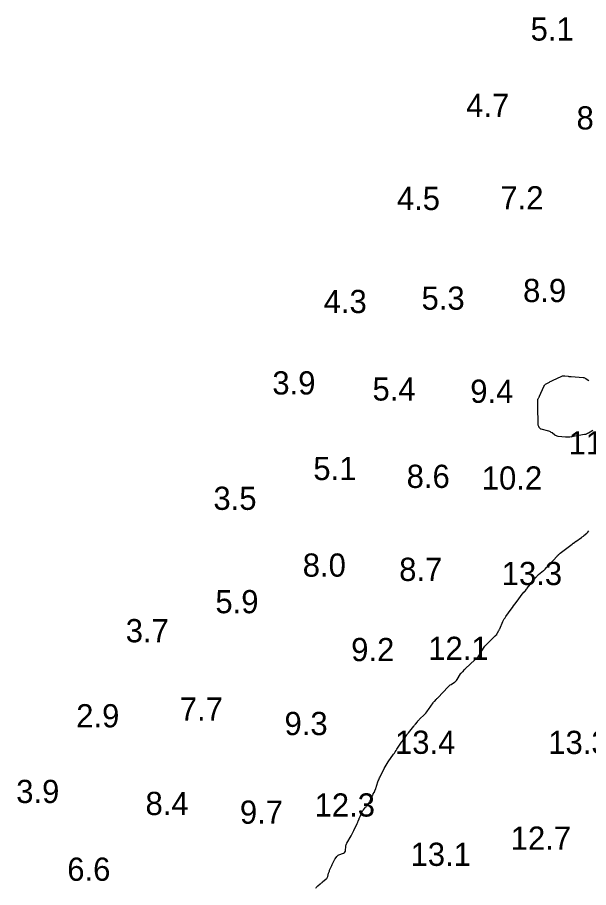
# Model space of a CAD drawing. Extents: x 815352 to 820877, y 582403 to 597439.
# Drawn here: x 819617 to 819740.1, y 588634.3 to 588821.8 of the extents above; entities that cross this region are included whole.
import ezdxf

# ---------------------------------------------------------------- set-up
doc = ezdxf.new("R2010")
doc.units = 0
doc.layers.add('V-CONT-EL12', color=7, linetype='Continuous')
doc.layers.add('V-TOPO-SOUN', color=7, linetype='Continuous')

msp = doc.modelspace()

# ---------------------------------------------------------------- linework, layer by layer
at = {"layer": 'V-CONT-EL12'}
for points in [[(819741, 588732.76), (819740.07, 588732.22), (819739.87, 588732.11), (819739.65, 588732.02), (819739.43, 588731.95), (819739.21, 588731.9), (819736.41, 588731.41), (819736.08, 588731.36), (819735.76, 588731.34), (819735.43, 588731.34), (819735.1, 588731.36), (819733.52, 588731.52), (819733.33, 588731.55), (819733.16, 588731.61), (819732.99, 588731.69), (819732.83, 588731.8), (819732.22, 588732.27), (819732.06, 588732.38), (819731.9, 588732.47), (819731.72, 588732.55), (819731.54, 588732.61), (819729.89, 588733.06), (819729.83, 588733.08), (819729.76, 588733.11), (819729.71, 588733.16), (819729.66, 588733.21), (819729.47, 588733.44), (819729.43, 588733.49), (819729.39, 588733.55), (819729.36, 588733.6), (819729.34, 588733.67), (819729.25, 588733.92), (819729.24, 588733.98), (819729.22, 588734.04), (819729.21, 588734.11), (819729.21, 588734.17), (819729.13, 588737.92), (819729.13, 588738.07), (819729.13, 588738.23), (819729.13, 588738.38), (819729.13, 588738.54), (819729.13, 588739.32), (819729.13, 588739.4), (819729.15, 588739.47), (819729.17, 588739.54), (819729.21, 588739.61), (819729.38, 588739.87), (819729.42, 588739.94), (819729.46, 588740.01), (819729.5, 588740.07), (819729.53, 588740.15), (819730.48, 588742.28), (819730.57, 588742.45), (819730.69, 588742.6), (819730.82, 588742.73), (819730.98, 588742.83), (819731.66, 588743.22), (819731.83, 588743.31), (819732, 588743.4), (819732.17, 588743.49), (819732.35, 588743.57), (819734.34, 588744.47), (819734.5, 588744.53), (819734.66, 588744.57), (819734.83, 588744.58), (819735, 588744.57), (819735.68, 588744.47), (819735.85, 588744.45), (819736.02, 588744.43), (819736.19, 588744.41), (819736.36, 588744.4), (819738.92, 588744.22), (819739.08, 588744.2), (819739.23, 588744.16), (819739.37, 588744.09), (819739.5, 588744.01), (819740.01, 588743.61), (819740.14, 588743.51)], [(819681.29, 588634.15), (819681.4, 588634.27), (819681.51, 588634.39), (819681.63, 588634.51), (819681.76, 588634.62), (819682.28, 588635.04), (819682.41, 588635.15), (819682.54, 588635.25), (819682.67, 588635.36), (819682.79, 588635.47), (819683.54, 588636.11), (819683.66, 588636.23), (819683.76, 588636.37), (819683.84, 588636.51), (819683.89, 588636.67), (819684.08, 588637.35), (819684.12, 588637.51), (819684.18, 588637.67), (819684.24, 588637.82), (819684.3, 588637.98), (819684.57, 588638.59), (819684.64, 588638.75), (819684.7, 588638.9), (819684.77, 588639.05), (819684.84, 588639.21), (819685.18, 588639.98), (819685.24, 588640.11), (819685.31, 588640.24), (819685.39, 588640.36), (819685.48, 588640.48), (819685.83, 588640.94), (819685.93, 588641.05), (819686.03, 588641.14), (819686.15, 588641.22), (819686.28, 588641.28), (819687.31, 588641.7), (819687.48, 588641.79), (819687.6, 588641.92), (819687.68, 588642.08), (819687.71, 588642.26), (819687.76, 588643.08), (819687.79, 588643.29), (819687.84, 588643.48), (819687.91, 588643.67), (819688, 588643.85), (819688.93, 588645.39), (819689.1, 588645.67), (819689.25, 588645.96), (819689.4, 588646.25), (819689.54, 588646.55), (819690.25, 588648.1), (819690.3, 588648.22), (819690.35, 588648.34), (819690.4, 588648.46), (819690.45, 588648.58), (819690.64, 588649.06), (819690.69, 588649.19), (819690.74, 588649.31), (819690.79, 588649.43), (819690.84, 588649.55), (819691.22, 588650.41), (819691.29, 588650.57), (819691.38, 588650.72), (819691.47, 588650.86), (819691.58, 588650.99), (819692.05, 588651.57), (819692.14, 588651.68), (819692.23, 588651.79), (819692.32, 588651.9), (819692.41, 588652.02), (819692.75, 588652.48), (819692.83, 588652.6), (819692.9, 588652.72), (819692.97, 588652.84), (819693.03, 588652.97), (819693.53, 588654.12), (819693.57, 588654.2), (819693.61, 588654.28), (819693.66, 588654.37), (819693.7, 588654.45), (819693.89, 588654.76), (819693.94, 588654.85), (819693.98, 588654.93), (819694.02, 588655.01), (819694.05, 588655.1), (819694.24, 588655.64), (819694.28, 588655.76), (819694.32, 588655.87), (819694.36, 588655.99), (819694.4, 588656.11), (819694.79, 588657.23), (819694.88, 588657.45), (819694.97, 588657.67), (819695.06, 588657.89), (819695.17, 588658.11), (819696.08, 588659.91), (819696.27, 588660.28), (819696.47, 588660.64), (819696.69, 588660.99), (819696.92, 588661.33), (819698.07, 588662.98), (819698.26, 588663.25), (819698.44, 588663.53), (819698.62, 588663.8), (819698.81, 588664.07), (819699.8, 588665.59), (819699.84, 588665.66), (819699.89, 588665.72), (819699.93, 588665.79), (819699.98, 588665.85), (819700.2, 588666.16), (819700.23, 588666.2), (819700.26, 588666.24), (819700.29, 588666.28), (819700.32, 588666.32), (819700.44, 588666.47), (819700.46, 588666.5), (819700.49, 588666.54), (819700.52, 588666.58), (819700.55, 588666.62), (819700.95, 588667.17), (819701.02, 588667.28), (819701.1, 588667.38), (819701.18, 588667.49), (819701.26, 588667.59), (819702.41, 588669.02), (819702.51, 588669.15), (819702.61, 588669.27), (819702.71, 588669.39), (819702.8, 588669.51), (819703.2, 588670), (819703.3, 588670.12), (819703.4, 588670.24), (819703.51, 588670.36), (819703.61, 588670.47), (819704.78, 588671.64), (819705, 588671.88), (819705.22, 588672.12), (819705.42, 588672.38), (819705.61, 588672.64), (819706.63, 588674.1), (819706.7, 588674.19), (819706.77, 588674.29), (819706.85, 588674.38), (819706.93, 588674.46), (819707.26, 588674.81), (819707.34, 588674.9), (819707.42, 588674.98), (819707.51, 588675.07), (819707.59, 588675.16), (819709.81, 588677.53), (819709.96, 588677.68), (819710.12, 588677.82), (819710.28, 588677.95), (819710.46, 588678.06), (819711.18, 588678.51), (819711.35, 588678.63), (819711.5, 588678.77), (819711.64, 588678.92), (819711.76, 588679.09), (819712.49, 588680.31), (819712.53, 588680.38), (819712.58, 588680.44), (819712.63, 588680.5), (819712.69, 588680.55), (819712.94, 588680.76), (819713, 588680.81), (819713.05, 588680.86), (819713.11, 588680.92), (819713.16, 588680.98), (819713.36, 588681.24), (819713.41, 588681.3), (819713.47, 588681.36), (819713.52, 588681.42), (819713.58, 588681.48), (819715.61, 588683.37), (819715.66, 588683.41), (819715.71, 588683.46), (819715.76, 588683.5), (819715.81, 588683.54), (819716.03, 588683.69), (819716.09, 588683.73), (819716.13, 588683.77), (819716.18, 588683.82), (819716.22, 588683.88), (819716.44, 588684.24), (819716.49, 588684.31), (819716.54, 588684.39), (819716.59, 588684.47), (819716.64, 588684.55), (819717.44, 588685.83), (819717.59, 588686.07), (819717.76, 588686.29), (819717.94, 588686.5), (819718.14, 588686.71), (819719.99, 588688.49), (819720.03, 588688.53), (819720.06, 588688.57), (819720.1, 588688.61), (819720.13, 588688.64), (819720.29, 588688.82), (819720.32, 588688.85), (819720.34, 588688.88), (819720.36, 588688.91), (819720.37, 588688.94), (819720.43, 588689.07), (819720.45, 588689.1), (819720.46, 588689.13), (819720.48, 588689.16), (819720.5, 588689.19), (819720.76, 588689.66), (819720.8, 588689.75), (819720.85, 588689.84), (819720.9, 588689.93), (819720.94, 588690.02), (819721.65, 588691.58), (819721.78, 588691.87), (819721.94, 588692.15), (819722.1, 588692.42), (819722.28, 588692.68), (819723.43, 588694.29), (819723.69, 588694.64), (819723.94, 588695), (819724.2, 588695.35), (819724.46, 588695.7), (819726.02, 588697.76), (819726.06, 588697.81), (819726.1, 588697.86), (819726.15, 588697.91), (819726.19, 588697.95), (819726.38, 588698.14), (819726.42, 588698.18), (819726.47, 588698.23), (819726.51, 588698.28), (819726.55, 588698.33), (819726.71, 588698.56), (819726.75, 588698.61), (819726.79, 588698.67), (819726.83, 588698.72), (819726.87, 588698.77), (819727.84, 588700.03), (819727.95, 588700.18), (819728.07, 588700.32), (819728.19, 588700.47), (819728.31, 588700.61), (819728.78, 588701.19), (819728.91, 588701.33), (819729.04, 588701.46), (819729.17, 588701.59), (819729.31, 588701.71), (819730.4, 588702.58), (819730.49, 588702.65), (819730.57, 588702.73), (819730.65, 588702.81), (819730.73, 588702.89), (819731.02, 588703.22), (819731.1, 588703.3), (819731.17, 588703.38), (819731.25, 588703.47), (819731.32, 588703.55), (819733.39, 588705.76), (819733.42, 588705.8), (819733.45, 588705.83), (819733.48, 588705.86), (819733.51, 588705.9), (819733.63, 588706.03), (819733.65, 588706.06), (819733.68, 588706.09), (819733.71, 588706.12), (819733.74, 588706.14), (819733.87, 588706.24), (819733.9, 588706.26), (819733.93, 588706.28), (819733.96, 588706.31), (819733.99, 588706.33), (819736.55, 588708.31), (819736.62, 588708.36), (819736.69, 588708.41), (819736.76, 588708.46), (819736.82, 588708.5), (819737.1, 588708.68), (819737.17, 588708.73), (819737.24, 588708.78), (819737.31, 588708.82), (819737.38, 588708.87), (819738.6, 588709.74), (819738.73, 588709.83), (819738.86, 588709.93), (819738.98, 588710.02), (819739.1, 588710.13), (819739.7, 588710.64), (819739.76, 588710.69), (819739.82, 588710.75), (819739.87, 588710.8), (819739.92, 588710.86), (819740.16, 588711.14)]]:
    msp.add_lwpolyline(points, dxfattribs=at)

# ---------------------------------------------------------------- texts
at = {"layer": 'V-TOPO-SOUN'}
for s, p in [('5.1', (819727.6, 588816.82)), ('4.7', (819713.71, 588800.35)), ('8.8', (819737.5, 588797.66)), ('4.5', (819698.78, 588780.3)), ('7.2', (819721.09, 588780.44)), ('8.9', (819725.98, 588760.46)), ('5.3', (819704.1, 588758.81)), ('4.3', (819683, 588758.09)), ('3.9', (819671.95, 588740.54)), ('5.4', (819693.53, 588739.23)), ('9.4', (819714.6, 588738.74)), ('11.5 ', (819735.78, 588727.61)), ('5.1', (819680.78, 588722.1)), ('8.6', (819700.89, 588720.4)), ('10.2 ', (819717.08, 588720.04)), ('3.5', (819659.25, 588715.67)), ('8.0', (819678.5, 588701.27)), ('8.7', (819699.28, 588700.35)), ('13.3 ', (819721.38, 588699.46)), ('5.9', (819659.68, 588693.39)), ('3.7', (819640.35, 588687.13)), ('9.2', (819688.94, 588683.06)), ('12.1 ', (819705.54, 588683.32)), ('2.9', (819629.69, 588668.79)), ('7.7', (819652, 588670.23)), ('9.3', (819674.57, 588667.12)), ('13.4 ', (819698.38, 588663.08)), ('13.3 ', (819731.41, 588663.05)), ('3.9', (819616.76, 588652.48)), ('8.4', (819644.62, 588649.89)), ('9.7', (819664.96, 588648.02)), ('12.3 ', (819681.05, 588649.56)), ('12.7 ', (819723.31, 588642.41)), ('13.1 ', (819701.73, 588638.93)), ('6.6', (819627.76, 588635.72))]:
    msp.add_text(s, height=5, dxfattribs=at).set_placement(p)

doc.saveas('drawing.dxf')
